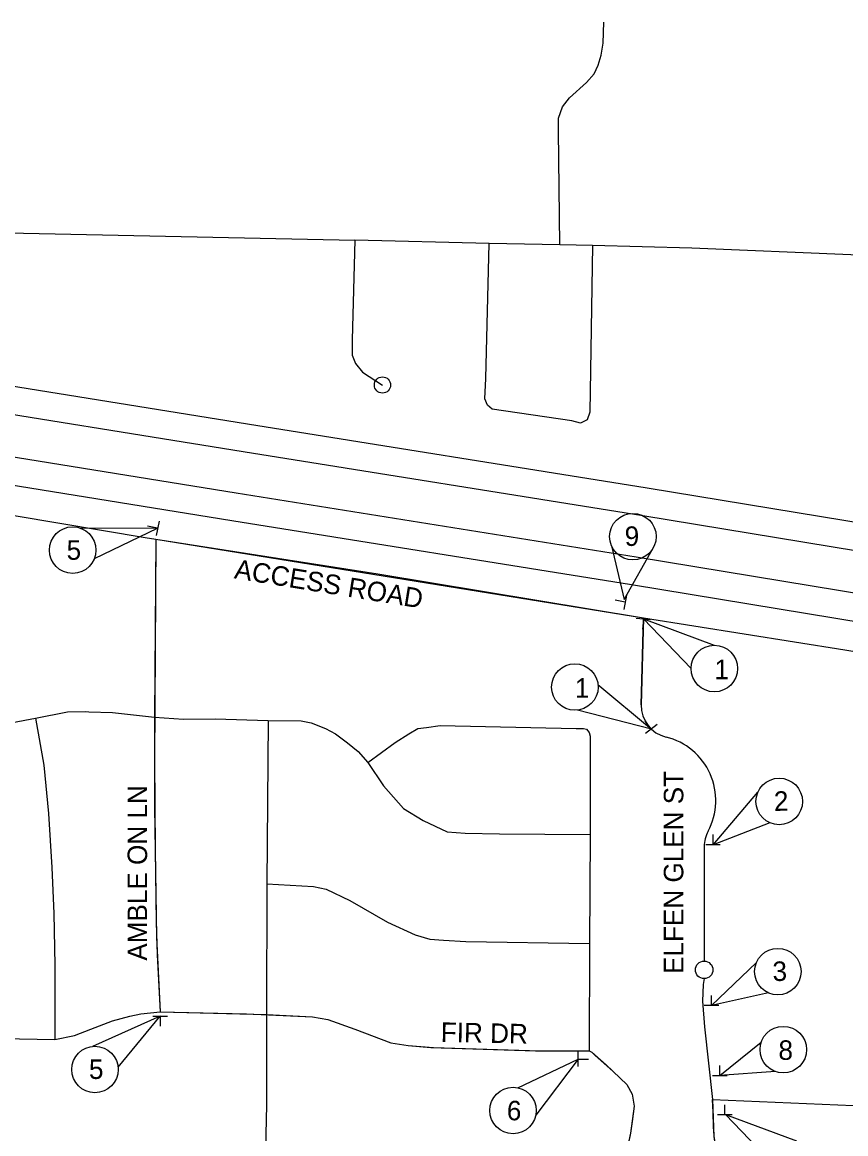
# Model space of a CAD drawing. Extents: x 185625 to 193575, y 1257500 to 1262681.
# Drawn here: x 187128 to 189658, y 1259263 to 1262681 of the extents above; entities that cross this region are included whole.
import ezdxf

# ---------------------------------------------------------------- set-up
doc = ezdxf.new("R2010")
doc.units = 0
for name, color, linetype in [('10', 7, 'Continuous'), ('Level 3', 7, 'Continuous'), ('Level 8', 7, 'Continuous')]:
    doc.layers.add(name, color=color, linetype=linetype)

msp = doc.modelspace()

# ---------------------------------------------------------------- linework, layer by layer
at = {"layer": '10'}
for points in [[(188779.5, 1261996.5), (188775.9, 1262346.8), (188775.9, 1262386.1), (188788.4, 1262420.1), (188809.9, 1262448.7), (188861.7, 1262495.2), (188884.9, 1262522), (188897.4, 1262548.8), (188906.4, 1262579.2), (188913.5, 1262616.7), (188914.8, 1262680.7)], [(186840.7, 1262038.4), (188150.6, 1262010.8)], [(188150.6, 1262010.8), (188141.7, 1261704.1), (188141.7, 1261656.9), (188151.9, 1261631.9), (188174.1, 1261605.1), (188235.1, 1261565.3)], [(191607.1, 1261902.2), (190996, 1261923), (190239.8, 1261948.5), (189882, 1261957.3), (189673.6, 1261965.3), (189185.3, 1261986), (188879.9, 1261994.5), (188779.5, 1261996.5), (188563.3, 1262000.1), (188150.6, 1262010.8)], [(188879.9, 1261994.5), (188872.4, 1261481.8), (188863.5, 1261458.6), (188843.8, 1261447.8), (188817, 1261455), (188572.3, 1261490.7), (188558, 1261503.3), (188549, 1261522.9), (188552.6, 1261585.5), (188563.3, 1262000.1)], [(193575.5, 1260557.6), (193212.7, 1260596.5), (192742.7, 1260653.6), (192330.9, 1260716.5), (191888.1, 1260787.1), (191307.8, 1260876.8), (190478.8, 1261007.5), (190038.6, 1261084.8), (189048.5, 1261248.2), (187820.3, 1261444.8), (186840.7, 1261603.3)], [(186840.7, 1261517.2), (187806.8, 1261360.9), (189034.8, 1261164.3), (190024.3, 1261001), (190464.9, 1260923.6), (191294.7, 1260792.9), (191874.9, 1260703.1), (192317.8, 1260632.5), (192731.2, 1260569.4), (193203.1, 1260512.1), (193575.5, 1260472.1)], [(193575.5, 1260341.4), (193188.3, 1260382.9), (192713.5, 1260440.6), (192297.7, 1260504), (191854.7, 1260574.7), (191274.6, 1260664.4), (190443.5, 1260795.4), (190002.5, 1260872.9), (189014, 1261035.9), (187786.1, 1261232.6), (186840.7, 1261385.5)], [(186840.7, 1261299.4), (187772.6, 1261148.7), (189000.3, 1260952), (189988.2, 1260789.1), (190429.5, 1260711.5), (191261.5, 1260580.4), (191841.6, 1260490.7), (192284.6, 1260420), (192702, 1260356.4), (193178.6, 1260298.5), (193575.5, 1260255.9)], [(191582.4, 1259981.2), (191550.8, 1259987.2), (191524.3, 1260006.5), (191500.2, 1260059.6), (191471.2, 1260173), (191442.3, 1260243), (191410.9, 1260284), (191348.2, 1260337.1), (191275.8, 1260382.9), (191155.2, 1260424), (190983.1, 1260495.9), (190840.8, 1260546.5), (190511.6, 1260605.2), (189655.3, 1260749.8), (189036.5, 1260848.7), (188221.1, 1260983.9), (187505.6, 1261095.4), (186840.7, 1261207.7)], [(187539.2, 1261090.2), (187534.3, 1260544.2), (187534.3, 1260267.1), (187540.8, 1259867.4), (187552.1, 1259638.3)], [(187099, 1260527.9), (187168.8, 1260540.9), (187267.9, 1260560.4), (187323.1, 1260562), (187332.9, 1260560.4), (187406, 1260558.8), (187534.3, 1260544.2), (187623.6, 1260537.7), (187721.1, 1260539.3), (187883.5, 1260534.4), (187985, 1260533.3), (188015.9, 1260526.8), (188059.7, 1260508.9), (188090.6, 1260492.6), (188128, 1260465), (188160.5, 1260439), (188189.7, 1260404.9), (188238.4, 1260333.4), (188300.1, 1260263.5), (188360.2, 1260226.2), (188433.3, 1260192.1), (188488.6, 1260187.2), (188594.1, 1260185.6), (188873.5, 1260183.9)], [(187883.5, 1260534.4), (187880.3, 1260032.1), (187878.6, 1259630.2), (187878.6, 1259351.3), (187877, 1259262), (187877, 1259239.2), (187870.5, 1259218.1), (187842.9, 1259187.2), (187779.5, 1259122.2), (187375.1, 1258769.8), (187316.2, 1258711.1), (187305.5, 1258693.6), (187276, 1258646.3), (187237, 1258560.8), (187188.3, 1258468.2), (187157.4, 1258411.3), (187134.7, 1258375.6), (187105.4, 1258348), (186996.6, 1258253.7), (186894.3, 1258166), (186840.7, 1258117.1)], [(187168.8, 1260540.9), (187194.8, 1260397.1), (187209.4, 1260247.6), (187219.2, 1260081.9), (187225.7, 1259940.5), (187228.9, 1259781.3), (187228.5, 1259552.7)], [(188189.7, 1260404.9), (188274.2, 1260466.7), (188316.4, 1260492.6), (188344, 1260508.9), (188370, 1260512.1), (188412.2, 1260518.6), (188829.7, 1260508.9), (188852.4, 1260508.9), (188862.1, 1260507.3), (188870.3, 1260497.5), (188873.5, 1260486.1), (188873.5, 1260183.9), (188871.1, 1259848.5), (188869.5, 1259518.6), (188878.4, 1259513.8), (188922.2, 1259474.8), (188985.6, 1259414.7), (189001.8, 1259385.5), (189008.3, 1259348.1), (188997, 1259265.2), (188980.7, 1259189.6)], [(187880.3, 1260032.1), (188023.2, 1260023.9), (188062.2, 1260015.8), (188135.3, 1259980.1), (188250.6, 1259913.5), (188335.1, 1259874.5), (188380.6, 1259861.5), (188422.8, 1259858.2), (188491, 1259855), (188871.1, 1259848.5)], [(189223.2, 1259740.5), (189219.9, 1259722.6), (189218.6, 1259670.6), (189223.9, 1259591.9), (189249.2, 1259369.2), (189253.2, 1259255.3), (189261.2, 1259208.6), (189272.1, 1259183.2), (189288.7, 1259158.9), (189325.2, 1259111.3), (189329.2, 1259091.3), (189309.2, 1258593.1), (189302.5, 1258514.4), (189279.9, 1258402.4), (189241.2, 1258261), (189218.6, 1258161)], [(186840.7, 1259561.8), (186902, 1259559.2), (187228.5, 1259552.7), (187288.6, 1259565.3), (187338.9, 1259584.8), (187405.5, 1259610.8), (187459.1, 1259625.4), (187493.2, 1259631.9), (187552.1, 1259638.3), (187878.6, 1259630.2)], [(187878.6, 1259630.2), (188020, 1259622.6), (188067.1, 1259614.5), (188149.9, 1259585.2), (188260.4, 1259543), (188314, 1259534.9), (188383.8, 1259528.4), (188705.4, 1259518.6), (188869.5, 1259518.6)], [(189249.2, 1259369.2), (189730.5, 1259348.6), (190331.7, 1259341.3), (191444.9, 1259295.9), (191572.7, 1259291.7)]]:
    msp.add_lwpolyline(points, dxfattribs=at)
for centre, radius in [((188235.1, 1261565.3), 25), ((189223.2, 1259767.3), 26.8)]:
    msp.add_circle(centre, radius, dxfattribs=at)
at = {"layer": 'Level 3'}
for p, q in [((187543.8, 1261125), (187513.7, 1261131.3)), ((187549, 1261146.8), (187539.8, 1261102.7)), ((188980.1, 1260897.5), (188949.9, 1260903.4)), ((188985, 1260919.4), (188976.4, 1260875.2)), ((189014.2, 1260848.6), (189058.9, 1260844.2)), ((189036.4, 1260845.7), (189033.4, 1260815.2)), ((189060.7, 1260508.1), (189041.6, 1260532.1)), ((189078.6, 1260521.5), (189043.4, 1260493.5)), ((189250.5, 1260152.5), (189250.5, 1260183.2)), ((189272.9, 1260151.9), (189227.9, 1260151.9)), ((189246.1, 1259657.9), (189246.1, 1259688.6)), ((189268.5, 1259657.3), (189223.5, 1259657.3)), ((187529.9, 1259625.1), (187574.9, 1259625.1)), ((187552.3, 1259624.4), (187552.3, 1259593.7)), ((188836.1, 1259470.3), (188836.1, 1259515.3)), ((188836.8, 1259492.7), (188867.5, 1259492.7)), ((189271.3, 1259442.5), (189271.3, 1259473.2)), ((189293.7, 1259441.9), (189248.7, 1259441.9)), ((189308.9, 1259321.5), (189263.9, 1259321.5)), ((189286.5, 1259322.1), (189286.5, 1259352.8))]:
    msp.add_line(p, q, dxfattribs=at)
at = {"layer": 'Level 8'}
msp.add_line((189223.2, 1260146.2), (189223.2, 1259794.1), dxfattribs=at)
for points in [[(187350.2, 1261032.4), (187544.4, 1261125), (187308.8, 1261124.6)], [(189036.5, 1260848.7), (187539.2, 1261090.2), (187534.3, 1260411.6), (187536.4, 1260135.5), (187540, 1259913.7), (187543.4, 1259813.9), (187552.1, 1259638.3), (187817.1, 1259631.7), (188020, 1259622.6), (188067.1, 1259614.5), (188149.9, 1259585.2), (188260.4, 1259543), (188314, 1259534.9), (188391.7, 1259528.1), (188687.2, 1259519.2), (188869.5, 1259518.6), (188878.4, 1259513.8), (188887.7, 1259505.5), (188943.7, 1259454.5), (188985.6, 1259414.7), (189001.8, 1259385.5), (189008.3, 1259348.1), (189001.8, 1259300.8), (188997, 1259265.2), (188989.6, 1259230.8)], [(188938.8, 1261070.5), (188978, 1260905.6), (189068.8, 1261068.3)], [(189030.1, 1260582.4), (189036.5, 1260848.7)], [(189036.5, 1260848.7), (189030.1, 1260582.4)], [(189036.5, 1260848.7), (189030.1, 1260582.4)], [(189183, 1260693.6), (189036.4, 1260846.4), (189254.5, 1260765.1)], [(188897.1, 1260644.9), (189061.1, 1260507.6), (188834.2, 1260565.8)], [(189425.5, 1260219.4), (189250.5, 1260151.9), (189388.1, 1260313.3)], [(189421.3, 1259696.2), (189246.1, 1259657.3), (189383.8, 1259790.1)], [(187423, 1259468.4), (187552.3, 1259625.1), (187344.5, 1259532.1)], [(189442.9, 1259454.6), (189271.3, 1259442.5), (189398.7, 1259545.5)], [(188650.8, 1259404.9), (188836.1, 1259492.7), (188706, 1259320.2)], [(189255, 1259245.2), (189252.2, 1259284.7), (189250.6, 1259329.4), (189249.2, 1259369.2), (189730.5, 1259348.6)], [(189435.6, 1259170), (189289, 1259322.8), (189507.1, 1259241.5)]]:
    msp.add_lwpolyline(points, dxfattribs=at)
for centre in [(189004.3, 1261099.2), (187283.4, 1261057.8), (189254.5, 1260693.6), (188826.1, 1260636.8), (189453.8, 1260285.1), (189449.5, 1259761.9), (189466.3, 1259522.1), (187351.9, 1259461), (188636.1, 1259335)]:
    msp.add_circle(centre, 71.5, dxfattribs=at)
for centre, radius, start, end in [((189130.1, 1260580), 100, 178.6215, 256.2712), ((189130.1, 1260580), 100, 178.6215, 256.2712), ((189130.1, 1260580), 100, 178.6215, 256.2712), ((189058.8, 1260288.4), 200.2, 331.7299, 76.2712), ((189058.8, 1260288.4), 200.2, 331.7299, 76.2712), ((189058.8, 1260288.4), 200.2, 331.7299, 76.2712), ((189323.2, 1260146.2), 100, 151.7299, 180), ((189323.2, 1260146.2), 100, 151.7299, 180)]:
    msp.add_arc(centre, radius, start, end, dxfattribs=at)

# ---------------------------------------------------------------- texts
for s, rotation, p in [('9', 0.4205, (188979.3, 1261070.5)), ('ACCESS ROAD', 350.8389, (187777.5, 1260971.2)), ('ELFEN GLEN ST', 90, (189159.3, 1259754.7)), ('AMBLE ON LN', 90, (187512.1, 1259795.5)), ('2', 1.5816, (189438.3, 1260255.7)), ('3', 1.5816, (189434, 1259732.6)), ('FIR DR', 358.8596, (188413.7, 1259546)), ('8', 359.6134, (189451.3, 1259490.7)), ('6', 357.5832, (188616.1, 1259305.8))]:
    msp.add_text(s, height=60, rotation=rotation, dxfattribs=at).set_placement(p)
for s, p in [('5', (187264.8, 1261028.1)), ('1', (189254.5, 1260660.9)), ('1', (188826.1, 1260604.1)), ('5', (187333.4, 1259431.9))]:
    msp.add_text(s, height=60, dxfattribs=at).set_placement(p)

doc.saveas('drawing.dxf')
